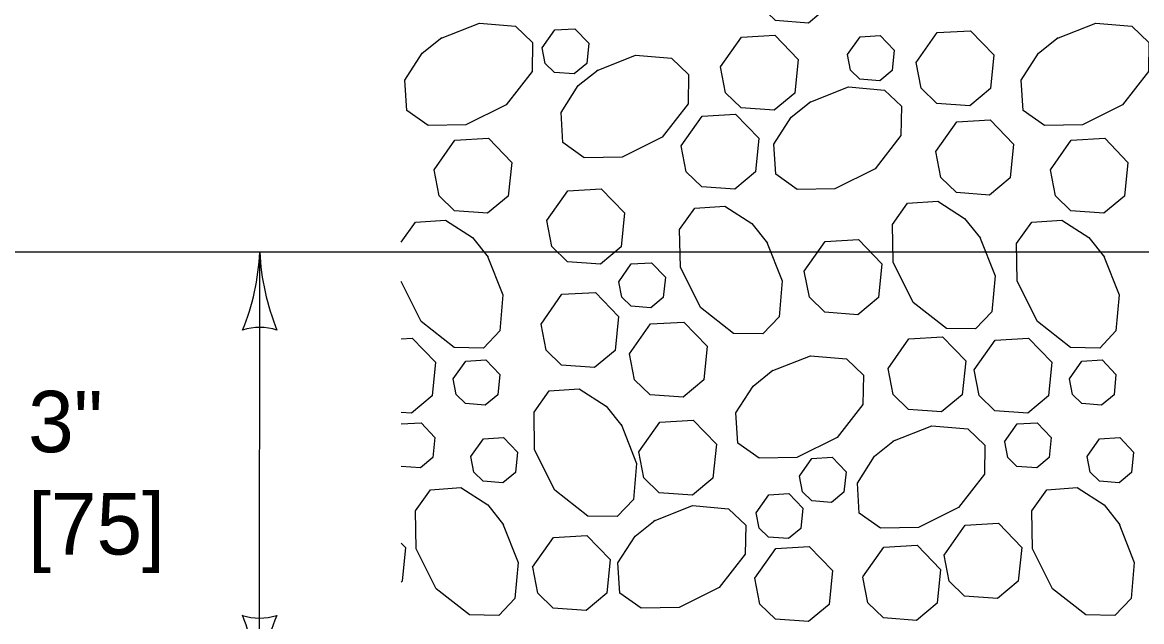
# Model space of a CAD drawing. Extents: x 49991.4 to 50021, y 49987.6 to 50011.4.
# Drawn here: x 50000.755 to 50001.85, y 49994.619 to 49995.205 of the extents above; entities that cross this region are included whole.
import ezdxf

# ---------------------------------------------------------------- set-up
doc = ezdxf.new("R2010")
doc.units = 0
for name, color, linetype in [('Level 1', 7, 'Continuous'), ('Level 2', 7, 'Continuous'), ('Level 3', 7, 'Continuous')]:
    doc.layers.add(name, color=color, linetype=linetype)

msp = doc.modelspace()

# ---------------------------------------------------------------- linework, layer by layer
at = {"layer": 'Level 1'}
for points in [[(50001.472, 49995.2465), (50001.4925, 49995.2757), (50001.5252, 49995.2776), (50001.5479, 49995.254), (50001.5446, 49995.2209), (50001.5244, 49995.2041), (50001.4921, 49995.2065), (50001.4769, 49995.2212), (50001.472, 49995.2465)], [(50001.1642, 49995.1889), (50001.2026, 49995.2041), (50001.2378, 49995.2011), (50001.2545, 49995.1852), (50001.254, 49995.1566), (50001.2286, 49995.1241), (50001.1893, 49995.1045), (50001.1523, 49995.1038), (50001.1315, 49995.1186), (50001.1295, 49995.1481), (50001.1464, 49995.1745), (50001.1658, 49995.1899)], [(50001.7674, 49995.1889), (50001.8057, 49995.2041), (50001.8409, 49995.2011), (50001.8576, 49995.1852), (50001.8571, 49995.1566), (50001.8317, 49995.1241), (50001.7925, 49995.1045), (50001.7555, 49995.1038), (50001.7346, 49995.1186), (50001.7327, 49995.1481), (50001.7496, 49995.1745), (50001.7689, 49995.1899)], [(50001.2639, 49995.1799), (50001.2762, 49995.1974), (50001.2958, 49995.1985), (50001.3094, 49995.1844), (50001.3075, 49995.1645), (50001.2953, 49995.1544), (50001.276, 49995.1558), (50001.2668, 49995.1647), (50001.2639, 49995.1799)], [(50001.4384, 49995.1612), (50001.4589, 49995.1903), (50001.4916, 49995.1922), (50001.5143, 49995.1686), (50001.511, 49995.1356), (50001.4908, 49995.1188), (50001.4585, 49995.1211), (50001.4433, 49995.1359), (50001.4384, 49995.1612)], [(50001.5627, 49995.1732), (50001.575, 49995.1907), (50001.5946, 49995.1918), (50001.6083, 49995.1776), (50001.6063, 49995.1578), (50001.5942, 49995.1477), (50001.5748, 49995.1491), (50001.5657, 49995.158), (50001.5627, 49995.1732)], [(50001.6299, 49995.1656), (50001.6503, 49995.1948), (50001.6831, 49995.1966), (50001.7058, 49995.1731), (50001.7025, 49995.14), (50001.6823, 49995.1232), (50001.65, 49995.1255), (50001.6348, 49995.1403), (50001.6299, 49995.1656)], [(50001.317, 49995.1574), (50001.3553, 49995.1726), (50001.3905, 49995.1696), (50001.4072, 49995.1537), (50001.4067, 49995.1251), (50001.3813, 49995.0926), (50001.3421, 49995.073), (50001.3051, 49995.0724), (50001.2842, 49995.0872), (50001.2823, 49995.1166), (50001.2992, 49995.143), (50001.3185, 49995.1584)], [(50001.5252, 49995.1265), (50001.5635, 49995.1417), (50001.5988, 49995.1386), (50001.6155, 49995.1227), (50001.615, 49995.0941), (50001.5896, 49995.0617), (50001.5503, 49995.042), (50001.5133, 49995.0414), (50001.4925, 49995.0562), (50001.4905, 49995.0857), (50001.5074, 49995.112), (50001.5268, 49995.1274)], [(50001.3998, 49995.0841), (50001.4203, 49995.1132), (50001.453, 49995.1151), (50001.4758, 49995.0915), (50001.4725, 49995.0585), (50001.4523, 49995.0417), (50001.42, 49995.044), (50001.4048, 49995.0587), (50001.3998, 49995.0841)], [(50001.6491, 49995.0784), (50001.6696, 49995.1075), (50001.7023, 49995.1094), (50001.7251, 49995.0858), (50001.7218, 49995.0527), (50001.7016, 49995.0359), (50001.6693, 49995.0383), (50001.6541, 49995.053), (50001.6492, 49995.0784)], [(50001.1581, 49995.0605), (50001.1785, 49995.0896), (50001.2113, 49995.0915), (50001.234, 49995.0679), (50001.2307, 49995.0349), (50001.2105, 49995.0181), (50001.1782, 49995.0204), (50001.163, 49995.0352), (50001.1581, 49995.0605)], [(50001.7612, 49995.0605), (50001.7816, 49995.0896), (50001.8144, 49995.0915), (50001.8371, 49995.0679), (50001.8338, 49995.0349), (50001.8136, 49995.0181), (50001.7813, 49995.0204), (50001.7661, 49995.0352), (50001.7612, 49995.0605)], [(50001.2684, 49995.0109), (50001.2889, 49995.0401), (50001.3216, 49995.0419), (50001.3444, 49995.0184), (50001.3411, 49994.9853), (50001.3209, 49994.9685), (50001.2886, 49994.9708), (50001.2734, 49994.9856), (50001.2684, 49995.0109)], [(50001.6918, 49994.9953), (50001.707, 49994.957), (50001.7039, 49994.9218), (50001.688, 49994.905), (50001.6594, 49994.9056), (50001.627, 49994.931), (50001.6073, 49994.9702), (50001.6067, 49995.0072), (50001.6215, 49995.028), (50001.651, 49995.03), (50001.6773, 49995.0131), (50001.6928, 49994.9938)], [(50001.4835, 49994.9904), (50001.4987, 49994.952), (50001.4957, 49994.9168), (50001.4798, 49994.9001), (50001.4512, 49994.9006), (50001.4187, 49994.926), (50001.3991, 49994.9653), (50001.3984, 49995.0023), (50001.4132, 49995.0231), (50001.4427, 49995.025), (50001.4691, 49995.0082), (50001.4845, 49994.9888)], [(50001.1259, 49994.9898), (50001.1399, 49995.0095), (50001.1693, 49995.0114), (50001.1957, 49994.9945), (50001.2111, 49994.9752)], [(50001.8133, 49994.9767), (50001.8285, 49994.9384), (50001.8254, 49994.9032), (50001.8095, 49994.8864), (50001.7809, 49994.887), (50001.7485, 49994.9124), (50001.7288, 49994.9516), (50001.7282, 49994.9886), (50001.743, 49995.0095), (50001.7724, 49995.0114), (50001.7988, 49994.9945), (50001.8142, 49994.9752)], [(50001.5203, 49994.9614), (50001.5408, 49994.9905), (50001.5735, 49994.9924), (50001.5963, 49994.9688), (50001.593, 49994.9358), (50001.5728, 49994.9189), (50001.5405, 49994.9213), (50001.5253, 49994.936), (50001.5203, 49994.9614)], [(50001.2101, 49994.9767), (50001.2253, 49994.9384), (50001.2223, 49994.9032), (50001.2064, 49994.8864), (50001.1778, 49994.887), (50001.1453, 49994.9124), (50001.1259, 49994.9513)], [(50001.3388, 49994.9512), (50001.3511, 49994.9687), (50001.3707, 49994.9698), (50001.3844, 49994.9557), (50001.3824, 49994.9358), (50001.3703, 49994.9258), (50001.3509, 49994.9272), (50001.3418, 49994.936), (50001.3388, 49994.9512)], [(50001.2627, 49994.9097), (50001.2832, 49994.9389), (50001.3159, 49994.9407), (50001.3386, 49994.9172), (50001.3353, 49994.8841), (50001.3151, 49994.8673), (50001.2828, 49994.8696), (50001.2676, 49994.8844), (50001.2627, 49994.9097)], [(50001.3493, 49994.8808), (50001.3698, 49994.9099), (50001.4025, 49994.9118), (50001.4252, 49994.8882), (50001.4219, 49994.8552), (50001.4017, 49994.8384), (50001.3694, 49994.8407), (50001.3542, 49994.8554), (50001.3493, 49994.8808)], [(50001.1259, 49994.8955), (50001.1367, 49994.8961), (50001.1595, 49994.8725), (50001.1562, 49994.8395), (50001.136, 49994.8227), (50001.1259, 49994.8234)], [(50001.6023, 49994.8663), (50001.6228, 49994.8955), (50001.6555, 49994.8973), (50001.6783, 49994.8738), (50001.675, 49994.8407), (50001.6548, 49994.8239), (50001.6225, 49994.8263), (50001.6073, 49994.841), (50001.6023, 49994.8663)], [(50001.6866, 49994.8651), (50001.7071, 49994.8942), (50001.7398, 49994.8961), (50001.7626, 49994.8725), (50001.7593, 49994.8395), (50001.7391, 49994.8227), (50001.7068, 49994.825), (50001.6916, 49994.8398), (50001.6866, 49994.8651)], [(50001.1768, 49994.8561), (50001.189, 49994.8736), (50001.2087, 49994.8747), (50001.2223, 49994.8605), (50001.2203, 49994.8407), (50001.2082, 49994.8306), (50001.1888, 49994.832), (50001.1797, 49994.8409), (50001.1768, 49994.8561)], [(50001.488, 49994.8637), (50001.5264, 49994.8789), (50001.5616, 49994.8758), (50001.5783, 49994.8599), (50001.5778, 49994.8313), (50001.5524, 49994.7989), (50001.5131, 49994.7792), (50001.4761, 49994.7786), (50001.4553, 49994.7934), (50001.4533, 49994.8229), (50001.4702, 49994.8492), (50001.4896, 49994.8646)], [(50001.7799, 49994.8561), (50001.7921, 49994.8736), (50001.8118, 49994.8747), (50001.8254, 49994.8605), (50001.8235, 49994.8407), (50001.8113, 49994.8306), (50001.792, 49994.832), (50001.7828, 49994.8409), (50001.7799, 49994.8561)], [(50001.341, 49994.8118), (50001.3562, 49994.7735), (50001.3531, 49994.7383), (50001.3372, 49994.7216), (50001.3086, 49994.7221), (50001.2762, 49994.7475), (50001.2565, 49994.7867), (50001.2559, 49994.8238), (50001.2707, 49994.8446), (50001.3002, 49994.8466), (50001.3265, 49994.8296), (50001.3419, 49994.8103)], [(50001.1259, 49994.8121), (50001.1453, 49994.8132), (50001.1589, 49994.799), (50001.1569, 49994.7792), (50001.1448, 49994.7691), (50001.1259, 49994.7705)], [(50001.3584, 49994.7849), (50001.3789, 49994.814), (50001.4116, 49994.8159), (50001.4343, 49994.7923), (50001.431, 49994.7593), (50001.4108, 49994.7425), (50001.3785, 49994.7448), (50001.3633, 49994.7595), (50001.3584, 49994.7849)], [(50001.607, 49994.7952), (50001.6453, 49994.8104), (50001.6805, 49994.8073), (50001.6972, 49994.7914), (50001.6967, 49994.7629), (50001.6713, 49994.7304), (50001.6321, 49994.7108), (50001.5951, 49994.7101), (50001.5742, 49994.7249), (50001.5723, 49994.7544), (50001.5892, 49994.7807), (50001.6085, 49994.7962)], [(50001.7164, 49994.7946), (50001.7287, 49994.8121), (50001.7484, 49994.8132), (50001.762, 49994.799), (50001.76, 49994.7792), (50001.7479, 49994.7691), (50001.7285, 49994.7705), (50001.7194, 49994.7794), (50001.7165, 49994.7946)], [(50001.194, 49994.7802), (50001.2063, 49994.7977), (50001.226, 49994.7988), (50001.2396, 49994.7846), (50001.2376, 49994.7648), (50001.2255, 49994.7547), (50001.2061, 49994.7561), (50001.197, 49994.765), (50001.1941, 49994.7802)], [(50001.7971, 49994.7802), (50001.8094, 49994.7977), (50001.8291, 49994.7988), (50001.8427, 49994.7846), (50001.8407, 49994.7648), (50001.8286, 49994.7547), (50001.8092, 49994.7561), (50001.8001, 49994.765), (50001.7972, 49994.7802)], [(50001.5156, 49994.761), (50001.5279, 49994.7785), (50001.5475, 49994.7796), (50001.5612, 49994.7654), (50001.5592, 49994.7456), (50001.5471, 49994.7355), (50001.5277, 49994.7369), (50001.5186, 49994.7458), (50001.5156, 49994.761)], [(50001.225, 49994.7152), (50001.2402, 49994.6768), (50001.2372, 49994.6416), (50001.2213, 49994.6249), (50001.1927, 49994.6254), (50001.1602, 49994.6508), (50001.1406, 49994.6901), (50001.1399, 49994.7271), (50001.1547, 49994.7479), (50001.1842, 49994.7499), (50001.2106, 49994.733), (50001.226, 49994.7136)], [(50001.4733, 49994.7254), (50001.4856, 49994.7429), (50001.5053, 49994.744), (50001.5189, 49994.7299), (50001.5169, 49994.71), (50001.5048, 49994.7), (50001.4854, 49994.7014), (50001.4763, 49994.7102), (50001.4734, 49994.7254)], [(50001.8281, 49994.7152), (50001.8433, 49994.6768), (50001.8403, 49994.6416), (50001.8244, 49994.6249), (50001.7958, 49994.6254), (50001.7633, 49994.6508), (50001.7437, 49994.6901), (50001.743, 49994.7271), (50001.7578, 49994.7479), (50001.7873, 49994.7499), (50001.8137, 49994.733), (50001.8291, 49994.7136)], [(50001.3727, 49994.7171), (50001.411, 49994.7323), (50001.4462, 49994.7292), (50001.463, 49994.7133), (50001.4624, 49994.6848), (50001.437, 49994.6523), (50001.3978, 49994.6327), (50001.3608, 49994.632), (50001.34, 49994.6468), (50001.338, 49994.6763), (50001.3549, 49994.7026), (50001.3743, 49994.7181)], [(50001.6572, 49994.6839), (50001.6777, 49994.7131), (50001.7104, 49994.715), (50001.7331, 49994.6914), (50001.7298, 49994.6583), (50001.7096, 49994.6415), (50001.6773, 49994.6439), (50001.6621, 49994.6586), (50001.6572, 49994.6839)], [(50001.2545, 49994.6722), (50001.275, 49994.7013), (50001.3077, 49994.7032), (50001.3305, 49994.6796), (50001.3272, 49994.6466), (50001.307, 49994.6297), (50001.2747, 49994.6321), (50001.2595, 49994.6468), (50001.2546, 49994.6722)], [(50001.1259, 49994.6956), (50001.13, 49994.6914), (50001.1267, 49994.6583), (50001.1259, 49994.6576)], [(50001.472, 49994.6614), (50001.4925, 49994.6905), (50001.5252, 49994.6924), (50001.5479, 49994.6688), (50001.5446, 49994.6357), (50001.5244, 49994.6189), (50001.4921, 49994.6213), (50001.4769, 49994.636), (50001.472, 49994.6613)], [(50001.5777, 49994.6626), (50001.5982, 49994.6917), (50001.6309, 49994.6936), (50001.6536, 49994.67), (50001.6504, 49994.6369), (50001.6301, 49994.6201), (50001.5978, 49994.6225), (50001.5826, 49994.6372), (50001.5777, 49994.6625)]]:
    msp.add_lwpolyline(points, dxfattribs=at)
at = {"layer": 'Level 3'}
for p, q in [((50002.0526, 49994.98), (50000.5064, 49994.98)), ((50000.9873, 49994.549), (50000.9875, 49994.98))]:
    msp.add_line(p, q, dxfattribs=at)
for centre, radius, start, end in [((50000.7653, 49994.9891), 0.2223, 337.456, 357.6395), ((50001.2202, 49994.9915), 0.233, 182.8273, 202.0772), ((50000.9875, 49994.8518), 0.0548, 72.1388, 107.8612), ((50000.9873, 49994.6772), 0.0548, 252.1388, 287.8612), ((50000.7546, 49994.5375), 0.233, 2.8273, 22.0772), ((50001.2095, 49994.5398), 0.2223, 157.456, 177.6395)]:
    msp.add_arc(centre, radius, start, end, dxfattribs=at)

# ---------------------------------------------------------------- texts
at = {"layer": 'Level 2'}
for s, p in [('3"', (50000.7608, 49994.7845)), ('[75]', (50000.7608, 49994.6845))]:
    msp.add_text(s, height=0.06, dxfattribs=at).set_placement(p)

doc.saveas('drawing.dxf')
